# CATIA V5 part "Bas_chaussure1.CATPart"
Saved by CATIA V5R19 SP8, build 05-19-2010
Part number: Bas_chaussure1
Bounding box of the stored display mesh (mm): x -167.5 to -112, y -29.564 to 160.561, z -8.823 to 174.302
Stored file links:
  G:\EU_thinkMotion\CFAO_2010\MMS_groupe2\MMS_groupe2\A reprendre\jcauchy\Bas_chaussure1.CATPart
  G:\EU_thinkMotion\CFAO_2010\MMS_groupe2\MMS_groupe2\A reprendre\jcauchy\Roller.CATProduct
  G:\EU_thinkMotion\CFAO_2010\MMS_groupe2\MMS_groupe2\A reprendre\jcauchy\squelette_bas_chaussure1.CATPart
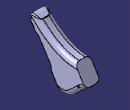
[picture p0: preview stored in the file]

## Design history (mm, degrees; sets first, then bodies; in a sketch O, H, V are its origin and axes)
Parameters
  Rayonfixation_baschaussure1 = 2.5 mm
  Largueurchaussure_baschaussure1 = 50 mm
  Longueurfixation_baschaussure1 = 20 mm
  Longueurcollier_baschaussure1 = 100 mm
Set1
  Plane1: stored without definition
  Sketch1 on Plane1, origin (-120, 0, 0), H (0, -1, 0), V (0, 0, 1)
    line L1 (-75.4569, -8.3621) -> (-43.9508, 42.7003)
    point P1 (-75.4569, -8.3621)
    point P2 (-43.9508, 42.7003)
    line L2 (8.5594, 127.8042) -> (29.5635, 161.8458)
    point P3 (8.5594, 127.8042)
    point P4 (29.5635, 161.8458)
    reference projected line E1 (-49.2018, 34.1899) -> (13.8105, 136.3146) from Line1
    reference projected line E2 (-49.2018, 34.1899) -> (13.8105, 136.3146) from Line2
    spline S1 through (-43.9508, 42.7003) (-43.6584, 52.696) (-26.3201, 83.2296) (-17.3964, 98.4529) (-7.1795, 113.1841) (1.476, 124.41) (8.5594, 127.8042)
    reference projected line E3 (-49.2018, 34.1899) -> (13.8105, 136.3146) from Line4
    spline S2 through (29.5635, 161.8458) (23.1681, 174.2174) (9.1583, 169.3669) (-0.4525, 164.5839)
    spline S3 through (-0.4525, 164.5839) (-27.8564, 141.1539) (-74.1478, 114.3142) (-123.8037, 103.7209)
    line L3 (-123.8037, 103.7209) -> (-160.5608, 44.1481)
    point P5 (-123.8037, 103.7209)
    point P6 (-160.5608, 44.1481)
    spline S4 through (-75.4569, -8.3621) (-95.6142, -6.7025) (-128.8056, 18.0291) (-160.5608, 44.1481)
    point P7 (-43.9508, 42.7003)
    point P8 (8.5594, 127.8042)
    point P9 (-43.6584, 52.696)
    point P11 (29.5635, 161.8458)
    point P12 (-0.4525, 164.5839)
    point P13 (-0.4525, 164.5839)
    point P14 (-123.8037, 103.7209)
    point P15 (-75.4569, -8.3621)
    point P16 (-160.5608, 44.1481)
    distance L1 P9 = 5
    distance L2 E3 = 0
    length L3 = 70
    distance P8 P7 = 100
    length L1 = 60
    length L2 = 40
    distance P15 P16 = 100 {= Longueurcollier_baschaussure1}
    coincidence: P3 L1, P2 P7, P8 P3, P14 P5, P16 P6, P15 P1, P11 P4, S2 P12, P12 P13
    parallelism: L2 L1, L2 E1, L1 E2
  Plane2: stored without definition
  Line1 to Line5: stored without definition
  Point1: stored without definition
  DatumPoint1
  DatumPoint2
  Plane3: stored without definition
  DatumPoint3
  Plane4: stored without definition
  DatumPoint4
  Plane5: stored without definition
  DatumPoint5
  Plane6: stored without definition
  DatumPoint6
  Plane7: stored without definition
  DatumPoint7
  DatumPoint8
Body1 (main body)
  Pad1: profile Sketch1, direction (-1, 0, 0), length 45 {= Longueurfixation_baschaussure1 +Largueurchaussure_baschaussure1 /2}, opposite side length 5 {= Largueurchaussure_baschaussure1/2 -Longueurfixation_baschaussure1}
  Fillet1: radius 15, on edge [face of Pad1 from Sketch1.S4 | end face of Pad1]; edge [start face of Pad1 | face of Pad1 from Sketch1.S4]; edge [start face of Pad1 | face of Pad1 from Sketch1.S3]; edge [face of Pad1 from Sketch1.S3 | end face of Pad1]
  Sketch2 on Plane3, origin (-123, 0, 0), H (0, -1, 0), V (0, 0, 1)
    circle A1 centre (-138.289, 42.1565) radius 2.5
    point P1 (-138.289, 42.1565)
    reference projected point E1 (-138.289, 42.1565) from vertex of DatumPoint3
    radius A1 = 2.5 {= Rayonfixation_baschaussure1}
    distance E1 P1 = 0
  Pad2: profile Sketch2, direction (1, 0, 0), length 11 {= Largueurchaussure_baschaussure1 /2-Longueurfixation_baschaussure1 +6mm}, opposite side length -5 {= -5mm}
  Fillet2: radius 5, on edge [face of Pad1 from Sketch1.S2 | face of Fillet1]
  Sketch3 on Plane7, origin (-120, 0, 0), H (0, -1, 0), V (0, 0, 1)
    circle A1 centre (-138.289, 42.1565) radius 2.5
    point P1 (-138.289, 42.1565)
    reference projected point E1 (-138.289, 42.1565) from vertex of DatumPoint8
    radius A1 = 2.5 {= Rayonfixation_baschaussure1}
    coincidence: P1 E1
  Pad3: profile Sketch3, direction (-1, 0, 0), length 47.5 {= Largueurchaussure_baschaussure1 /2+Longueurfixation_baschaussure1+Rayonfixation_baschaussure1}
